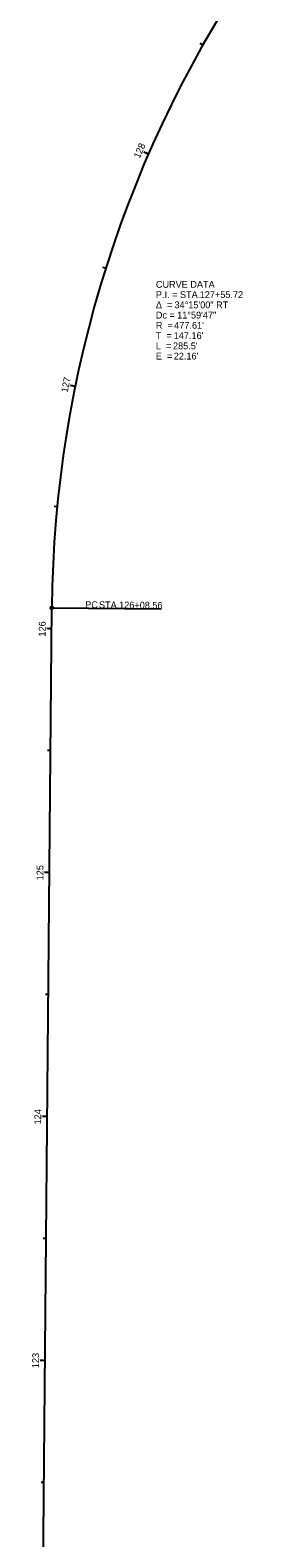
# Model space of a CAD drawing. Extents: x 177110 to 177558, y 286252 to 294117.
# Drawn here: x 177168 to 177263, y 288100 to 288718 of the extents above; entities that cross this region are included whole.
import ezdxf

# ---------------------------------------------------------------- set-up
doc = ezdxf.new("R2010")
doc.units = 0
for name, color, linetype in [('GE_X_Alignment_500_Cardinal_Points', 7, 'Continuous'), ('GE_X_Alignment_500_Curve_Data', 7, 'Continuous'), ('GE_X_Alignment_500_Stations', 7, 'Continuous'), ('RW_X_CL', 7, 'Continuous'), ('RW_X_CL_100_Cardinal_Points', 7, 'Continuous'), ('RW_X_CL_100_Curve_Data', 7, 'Continuous'), ('RW_X_CL_100_Stations', 7, 'Continuous')]:
    doc.layers.add(name, color=color, linetype=linetype)

msp = doc.modelspace()

# ---------------------------------------------------------------- linework, layer by layer
at = {"layer": 'GE_X_Alignment_500_Cardinal_Points'}
msp.add_line((177177.22, 288481.53), (177222.22, 288481.1), dxfattribs=at)
msp.add_circle((177177.22, 288481.53), 0.6, dxfattribs=at)
at = {"layer": 'GE_X_Alignment_500_Stations'}
for p, q in [((177216.83, 288667.52), (177215.73, 288668)), ((177186.8, 288572.33), (177185.63, 288572.56)), ((177177.15, 288472.97), (177175.95, 288472.98)), ((177176.25, 288372.97), (177174.25, 288372.99)), ((177175.35, 288272.98), (177174.15, 288272.99)), ((177174.45, 288172.98), (177173.25, 288172.99))]:
    msp.add_line(p, q, dxfattribs=at)
at = {"layer": 'RW_X_CL'}
msp.add_line((177168.31, 287489.01), (177177.22, 288481.53), dxfattribs=at)
msp.add_arc((177654.81, 288477.04), 477.61, 145.21153, 179.46165, dxfattribs=at)
at = {"layer": 'RW_X_CL_100_Cardinal_Points'}
msp.add_line((177177.22, 288481.53), (177222.22, 288481.1), dxfattribs=at)
msp.add_circle((177177.22, 288481.53), 0.6, dxfattribs=at)
at = {"layer": 'RW_X_CL_100_Stations'}
for p, q in [((177239.13, 288712.24), (177238.09, 288712.84)), ((177216.83, 288667.52), (177215, 288668.32)), ((177199.32, 288620.71), (177198.18, 288621.07)), ((177186.8, 288572.33), (177184.84, 288572.72)), ((177179.41, 288522.9), (177178.22, 288523.01)), ((177177.15, 288472.97), (177175.15, 288472.99)), ((177176.7, 288422.97), (177175.5, 288422.98)), ((177176.25, 288372.97), (177174.25, 288372.99)), ((177175.8, 288322.98), (177174.6, 288322.99)), ((177175.35, 288272.98), (177173.35, 288273)), ((177174.9, 288222.98), (177173.7, 288222.99)), ((177174.45, 288172.98), (177172.45, 288173)), ((177174, 288122.98), (177172.8, 288122.99))]:
    msp.add_line(p, q, dxfattribs=at)

# ---------------------------------------------------------------- texts
at = {"layer": 'GE_X_Alignment_500_Cardinal_Points'}
for s, p in [('PC', (177190.9, 288481.43)), (' STA. ', (177195.5, 288481.39)), ('126+08.56', (177204.82, 288481.3))]:
    msp.add_text(s, height=2.8, rotation=359.46165, dxfattribs=at).set_placement(p)
at = {"layer": 'GE_X_Alignment_500_Curve_Data'}
for s, p in [('CURVE DATA', (177219.9, 288612.73)), ('Δ  = ', (177219.9, 288604.33)), ('P.I. = STA. ', (177219.9, 288608.53)), ('34°15\'00" RT', (177227.54, 288604.33)), ('127+55.72', (177237.89, 288608.53)), ('Dc = ', (177219.9, 288600.13)), ('11°59\'47"', (177228.64, 288600.13)), ('T  = ', (177219.9, 288591.73)), ('R  = ', (177219.9, 288595.93)), ("147.16'", (177227.22, 288591.73)), ("477.61'", (177227.43, 288595.93)), ('L  = ', (177219.9, 288587.53)), ("285.5'", (177226.93, 288587.53)), ('E  = ', (177219.9, 288583.33)), ("22.16'", (177227.24, 288583.33))]:
    msp.add_text(s, height=2.8, dxfattribs=at).set_placement(p)
at = {"layer": 'GE_X_Alignment_500_Stations'}
msp.add_text('125', height=2.8, rotation=89.48526, dxfattribs=at).set_placement((177173.72, 288369.79))
at = {"layer": 'RW_X_CL_100_Cardinal_Points'}
for s, p in [('PC', (177190.9, 288481.43)), (' STA. ', (177195.5, 288481.39)), ('126+08.56', (177204.82, 288481.3))]:
    msp.add_text(s, height=2.8, rotation=359.46165, dxfattribs=at).set_placement(p)
at = {"layer": 'RW_X_CL_100_Curve_Data'}
for s, p in [('CURVE DATA', (177219.9, 288612.73)), ('Δ  = ', (177219.9, 288604.33)), ('P.I. = STA. ', (177219.9, 288608.53)), ('34°15\'00" RT', (177227.54, 288604.33)), ('127+55.72', (177237.89, 288608.53)), ('Dc = ', (177219.9, 288600.13)), ('11°59\'47"', (177228.64, 288600.13)), ('T  = ', (177219.9, 288591.73)), ('R  = ', (177219.9, 288595.93)), ("147.16'", (177227.22, 288591.73)), ("477.61'", (177227.43, 288595.93)), ('L  = ', (177219.9, 288587.53)), ("285.5'", (177226.93, 288587.53)), ('E  = ', (177219.9, 288583.33)), ("22.16'", (177227.24, 288583.33))]:
    msp.add_text(s, height=2.8, dxfattribs=at).set_placement(p)
at = {"layer": 'RW_X_CL_100_Stations'}
for s, rotation, p in [('128', 66.49548, (177213.24, 288665.54)), ('127', 78.49183, (177183.71, 288569.65)), ('126', 89.48526, (177174.62, 288469.74)), ('125', 89.48526, (177173.72, 288369.79)), ('124', 89.48526, (177172.82, 288269.72)), ('123', 89.48526, (177171.92, 288169.81))]:
    msp.add_text(s, height=2.8, rotation=rotation, dxfattribs=at).set_placement(p)

doc.saveas('drawing.dxf')
